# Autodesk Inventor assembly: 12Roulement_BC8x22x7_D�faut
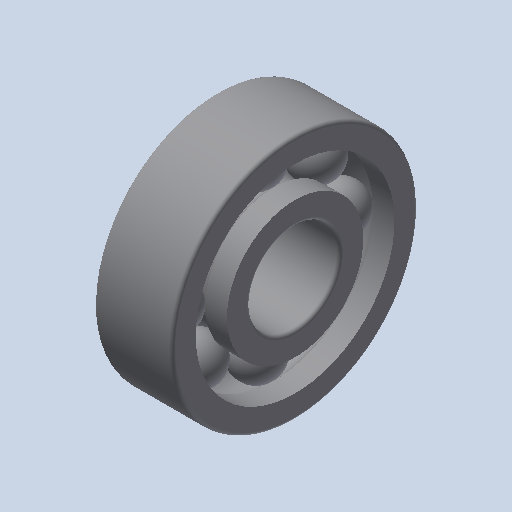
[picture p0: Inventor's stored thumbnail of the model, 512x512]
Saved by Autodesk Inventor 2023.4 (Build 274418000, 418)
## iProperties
Created: 2011-01
Part Number: 12Roulement_BC8x22x7_D�faut
Document SubType Name: Assembly
Designer: eric
Mass: 1.54909 g
Surface Area: 21.7227 cm^2
Volume: 1.54909 cm^3
Density: 1 g/cm^3
Author: eric
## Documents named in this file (4)
- C:\Users\bruno\Documents\1-Cours-2024-25\TSsI\7-Dynamique\chariot de golf\chariot_de_golf\chariot_de_golf_trolem\12Roulement_BC8x22x7_Defaut.iam
- C:\Users\bruno\Documents\1-Cours-2024-25\TSsI\7-Dynamique\chariot de golf\chariot_de_golf\chariot_de_golf_trolem\Roulement_r1rb_Bint16_Defaut.ipt
- C:\Users\bruno\Documents\1-Cours-2024-25\TSsI\7-Dynamique\chariot de golf\chariot_de_golf\chariot_de_golf_trolem\Roulement_r1rb_Eroul16_Defaut.ipt
- C:\Users\bruno\Documents\1-Cours-2024-25\TSsI\7-Dynamique\chariot de golf\chariot_de_golf\chariot_de_golf_trolem\Roulement_r1rb_Bext16_Defaut.ipt
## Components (10 placed, 3 different names)
1. Roulement_r1rb_Bint16_Defaut:1
2. Roulement_r1rb_Eroul16_Defaut:1
3. Roulement_r1rb_Eroul16_Defaut:2
4. Roulement_r1rb_Eroul16_Defaut:3
5. Roulement_r1rb_Eroul16_Defaut:4
6. Roulement_r1rb_Eroul16_Defaut:5
7. Roulement_r1rb_Eroul16_Defaut:6
8. Roulement_r1rb_Eroul16_Defaut:7
9. Roulement_r1rb_Bext16_Defaut:1
10. Roulement_r1rb_Eroul16_Defaut:8
